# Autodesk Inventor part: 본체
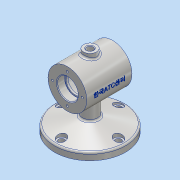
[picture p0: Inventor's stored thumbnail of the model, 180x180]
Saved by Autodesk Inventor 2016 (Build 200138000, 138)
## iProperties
Created: 2018-12
Part Number: 본체
Material: 알루미늄 6061
Document SubType Name: Modeling
Designer: 3sil_cad018
Density: 2.7 g/cm^3
Appearance: 알루미늄 - 평지
Author: 3sil_cad018
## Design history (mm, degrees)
sketch "스케치2"
  geometry: L1 (0, 0)-(-55, 0); L2 (-55, 0)-(-55, 11); L3 (-55, 11)-(0, 11); L4 (0, 11)-(0, 0); L5 (-55, 11)-(0, 25.737); L6 (0, 25.737)-(0, 11)
  constraints: 12 end point, 2 parallel, 1 horizontal, 1 perpendicular, 1 vertical
  dimensions: "d0" = 11 distance of L1.end L2.end; "d1" = 75 deg angle of L5 L2; "d2" = 110 diameter of L2 L4
revolve "회전1" sketch "스케치2" stored, may be unused: angle "d3" = 90 deg
node "작업 평면1"
sketch "스케치3" dims "d5" = 88
  geometry: 3 further points
  constraints: 2 horizontal alignment, 1 coincident, 2 other
hole "구멍1" sketch "스케치3" at (44, 0) diameter "d6" = 9; stored, may be unused: countersink angle "d10" = 90 deg, drill point angle "d12" = 118 deg; dims "d7" = 6, "d8" = 14, "d9" = 10, "d11" = 8
sketch "스케치4"
  geometry: L1 (0, 75)-(-35, 75); L2 (-35, 75)-(-35, 105); L3 (-35, 105)-(0, 105); L4 (0, 105)-(0, 75); L5 (55, 0)-(-55, 0) reference; L6 (-35, 91)-(-23, 91); L7 (-23, 91)-(-23, 89); L8 (-23, 89)-(-20, 89); L9 (-20, 89)-(-20, 100); L10 (-20, 100)-(0, 100); L11 (0, 75)-(35, 75); L12 (35, 75)-(35, 105); L13 (35, 105)-(0, 105); L14 (35, 91)-(23, 91); L15 (23, 91)-(23, 89); L16 (23, 89)-(20, 89); L17 (20, 89)-(20, 100); L18 (20, 100)-(0, 100); 1 further point
  constraints: 34 end point, 7 symmetric about line, 5 perpendicular, 4 point on line, 2 horizontal, 2 parallel
  dimensions: "d16" = 75 distance from line of L1.start L5; "d17" = 60 diameter of L3 L1; "d18" = 35 distance between parallel lines of L4 L2; "d19" = 32 diameter of L6 L1; "d20" = 28 diameter of L8 L1; "d21" = 50 diameter of L10 L1; "d22" = 20 distance from line of L4 L9.end; "d23" = 12 distance of L6.start L6.end
revolve "회전2" stored, may be unused: angle "d24" = 90 deg
node "작업 평면2"
sketch "스케치5"
  geometry: C1 r 10 at (0, 0); 1 further point
  constraints: 1 centre point, 1 coincident
  dimensions: "d26" = 20 diameter of C1
extrude "돌출1" join sketch "스케치5" stored distance "d27" = 10; taper "d28" = 0 deg
sketch "스케치6"
  geometry: C1 r 12 at (0, 0); 1 further point
  constraints: 1 centre point, 1 coincident
  dimensions: "d29" = 24 diameter of C1
extrude "돌출2" join sketch "스케치6" stored distance "d30" = 10; taper "d31" = 0 deg
fillet "모깎기1" dims "d32" = 3
revolve "회전3" stored, may be unused: angle "d33" = 90 deg
fillet "모깎기2" dims "d38" = 3
fillet "모깎기3" dims "d39" = 0.3
chamfer "모따기1" distance "d40" = 1; stored, may be unused: second distance "d41" = 2, angle "d42" = 45 deg
sketch "스케치7" dims "d43" = 46
  geometry: 4 further points
  constraints: 2 vertical alignment, 1 coincident, 2 other
hole "구멍2" sketch "스케치7" at (0, 23) diameter "d44" = 3.242; stored, may be unused: countersink angle "d48" = 90 deg, drill point angle "d50" = 118 deg; dims "d45" = 8, "d46" = 14, "d47" = 10, "d49" = 10
hole "구멍3" diameter "d56" = 10; stored, may be unused: countersink angle "d60" = 90 deg, drill point angle "d62" = 118 deg; dims "d54" = 10, "d55" = 10, "d57" = 8, "d58" = 14, "d59" = 10, "d61" = 10
chamfer "모따기2" distance "d63" = 1; stored, may be unused: second distance "d64" = 2, angle "d65" = 45 deg
node "작업 평면3"
sketch "스케치8"
  geometry: L1 (-35, 45)-(-35, 105) reference; 2 further points
  constraints: 1 other
  dimensions: "d67" = 35 distance from line of point (0, 75) L1; "d68" = 30 vertical distance of L1.end point (0, 75)
feature "엠보싱1" sketch "스케치8" dims "d0" = 11, "d1" = 75 deg, "d2" = 110, "d16" = 75, "d17" = 60, "d18" = 35, "d19" = 32, "d20" = 28, "d21" = 50, "d22" = 20, "d23" = 12, "d69" = 0.5, "d70" = 0
node "솔리드1"
pattern_circular "원형 패턴1" dims angle "d14" = 360 deg
pattern_circular "원형 패턴2" dims angle "d52" = 360 deg
mirror "대칭1"
other parameters: "d25" = -112, "d34" = 0.5, "d35" = 2, "d36" = 0
